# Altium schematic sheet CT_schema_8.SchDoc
size 274 x 160 mm
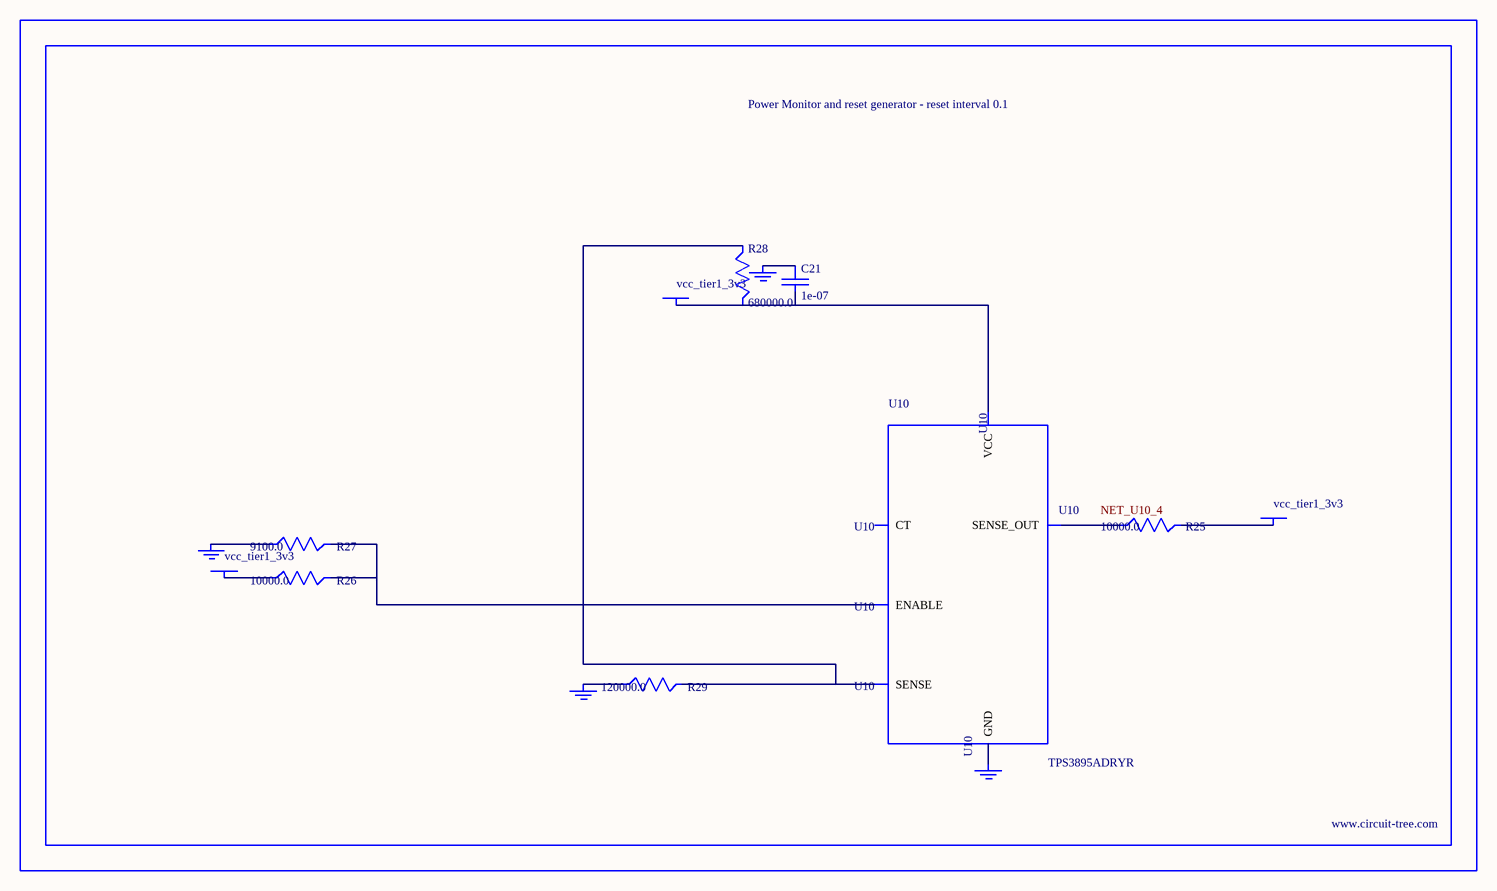
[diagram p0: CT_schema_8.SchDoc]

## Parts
BORDER7  (no value)
C21  1e-07  [C0402]
GND_INSTANCE_7_0  (no value)
GND_INSTANCE_7_1  (no value)
GND_INSTANCE_7_2  (no value)
GND_INSTANCE_7_3  (no value)
POWER_INSTANCE_7_0  vcc_tier1_3v3
POWER_INSTANCE_7_1  vcc_tier1_3v3
POWER_INSTANCE_7_2  vcc_tier1_3v3
R25  10000.0  [R0603]
R26  10000.0  [R0603]
R27  9100.0  [R0603]
R28  680000.0  [R0603]
R29  120000.0  [R0603]
U10  TPS3895ADRYR  [SON-6]

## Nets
NetC21_1: C21.1 GND_INSTANCE_7_2.0(GND)
NetC21_2: C21.2 POWER_INSTANCE_7_2.0(PWR) R28.2 U10.6(VCC)
NetGND_INSTANCE_7_0_0: GND_INSTANCE_7_0.0(GND) R27.1
NetGND_INSTANCE_7_1_0: GND_INSTANCE_7_1.0(GND) R29.1
NetGND_INSTANCE_7_3_0: GND_INSTANCE_7_3.0(GND) U10.2(GND)
NetPOWER_INSTANCE_7_0_0: POWER_INSTANCE_7_0.0(PWR) R26.1
NetPOWER_INSTANCE_7_1_0: POWER_INSTANCE_7_1.0(PWR) R25.2
NetR25_1: R25.1 U10.4(SENSE_OUT)
NetR26_2: R26.2 R27.2 U10.1(ENABLE)
NetR28_1: R28.1 R29.2 U10.3(SENSE)

Not connected (* = marked no-connect by the designer): U10 5(CT)

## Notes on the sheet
- Labels drawn without touching a wire or pin: NET_U10_4

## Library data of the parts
BORDER7 = BORDER_PAGE7
C21 = C0402C104K3RACTU
GND_INSTANCE_7_0-GND_INSTANCE_7_3 = GND
POWER_INSTANCE_7_0-POWER_INSTANCE_7_2 = PWR
R25 R26 = RC0603JR-0710KL
R27 = RC0603JR-079K1L
R28 = RC0603JR-07680KL
R29 = RC0603JR-07120KL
